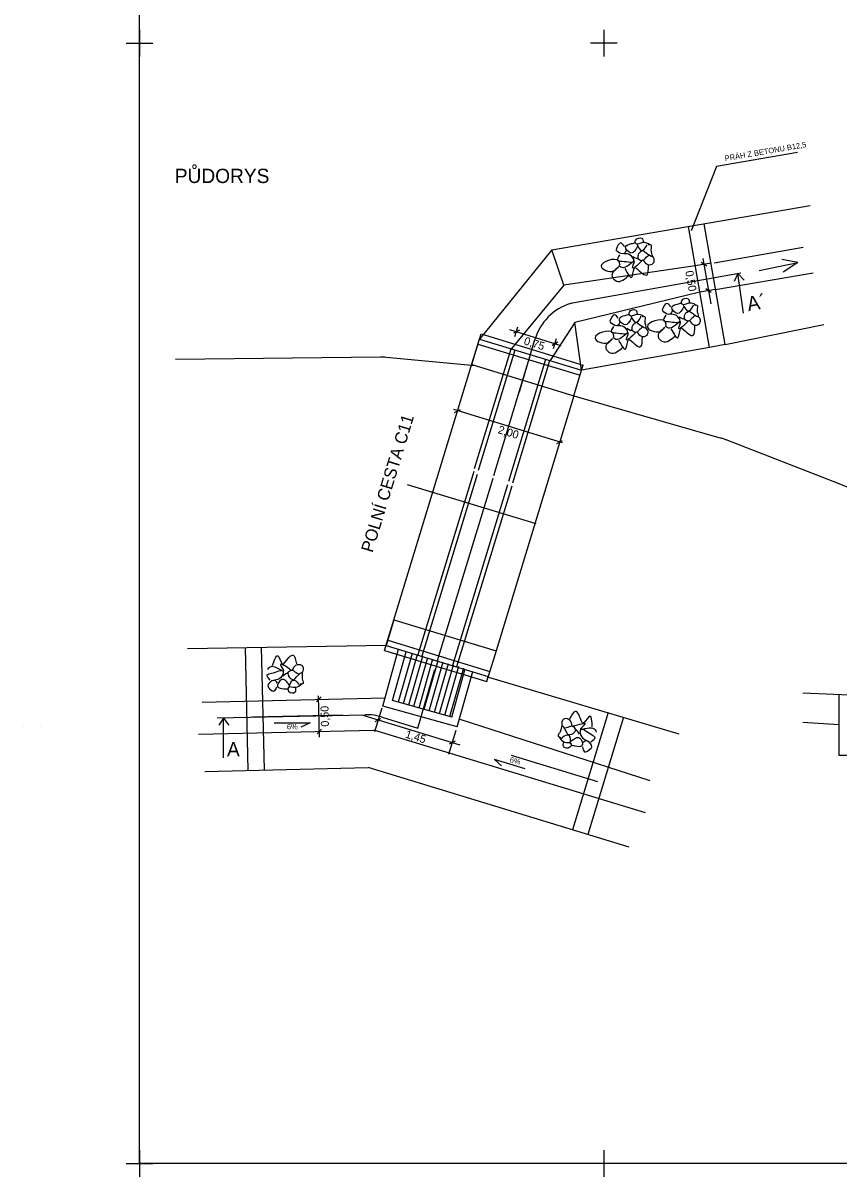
# Model space of a CAD drawing. Extents: x -463095.2 to -463031, y -1105061.3 to -1104976.3.
# Drawn here: x -463095.23 to -463064.66, y -1105061.31 to -1105018.06 of the extents above; entities that cross this region are included whole.
import ezdxf

# ---------------------------------------------------------------- set-up
doc = ezdxf.new("R2010")
doc.units = 0
for name, color, linetype in [('Implicitní', 7, 'Continuous'), ('Vrstva 14', 7, 'Continuous'), ('Vrstva 57', 7, 'Continuous')]:
    doc.layers.add(name, color=color, linetype=linetype)

msp = doc.modelspace()

# ---------------------------------------------------------------- linework, layer by layer
at = {"layer": 'Implicitní'}
for p, q in [((-463073.467, -1105018.311), (-463073.467, -1105019.311)), ((-463073.467, -1105018.311), (-463073.467, -1105019.311)), ((-463072.967, -1105018.811), (-463073.967, -1105018.811)), ((-463072.967, -1105018.811), (-463073.967, -1105018.811)), ((-463073.467, -1105060.311), (-463073.467, -1105061.311)), ((-463073.467, -1105060.311), (-463073.467, -1105061.311)), ((-463072.967, -1105060.811), (-463073.967, -1105060.811)), ((-463072.967, -1105060.811), (-463073.967, -1105060.811))]:
    msp.add_line(p, q, dxfattribs=at)
at = {"layer": 'Vrstva 14'}
for p, q in [((-463090.867, -1105018.311), (-463090.867, -1105019.311)), ((-463090.867, -1105018.312), (-463090.867, -1105019.312)), ((-463091.367, -1105018.811), (-463090.367, -1105018.811)), ((-463091.367, -1105018.812), (-463090.367, -1105018.812)), ((-463066.211, -1105022.907), (-463069.25, -1105023.431)), ((-463069.25, -1105023.431), (-463070.194, -1105025.844)), ((-463075.423, -1105026.566), (-463065.746, -1105024.899)), ((-463068.926, -1105030.115), (-463069.707, -1105025.581)), ((-463069.518, -1105030.217), (-463070.299, -1105025.683)), ((-463075.423, -1105026.566), (-463078.12, -1105029.897)), ((-463074.972, -1105027.879), (-463075.423, -1105026.566)), ((-463069.757, -1105026.885), (-463069.465, -1105028.58)), ((-463069.339, -1105027.046), (-463066.006, -1105026.464)), ((-463070.044, -1105027.162), (-463074.972, -1105027.879)), ((-463069.453, -1105027.06), (-463070.044, -1105027.162)), ((-463069.617, -1105027.179), (-463069.818, -1105027.035)), ((-463067.649, -1105027.337), (-463066.197, -1105027.037)), ((-463066.197, -1105027.037), (-463066.796, -1105026.917)), ((-463066.197, -1105027.037), (-463066.748, -1105027.399)), ((-463069.283, -1105028.045), (-463065.622, -1105027.418)), ((-463068.447, -1105027.453), (-463068.213, -1105027.694)), ((-463074.972, -1105027.879), (-463076.968, -1105030.304)), ((-463069.874, -1105028.147), (-463074.557, -1105029.284)), ((-463069.283, -1105028.045), (-463069.874, -1105028.147)), ((-463069.445, -1105028.162), (-463069.647, -1105028.019)), ((-463076.812, -1105029.811), (-463076.698, -1105029.441)), ((-463074.557, -1105029.284), (-463075.477, -1105030.708)), ((-463074.304, -1105031.072), (-463074.557, -1105029.284)), ((-463068.926, -1105030.115), (-463065.225, -1105029.359)), ((-463081.685, -1105041.577), (-463078.127, -1105029.896)), ((-463078.422, -1105030.863), (-463078.13, -1105029.906)), ((-463078.13, -1105029.906), (-463078.072, -1105029.715)), ((-463078.13, -1105029.906), (-463074.304, -1105031.072)), ((-463078.072, -1105029.715), (-463074.246, -1105030.88)), ((-463077.006, -1105029.551), (-463075.078, -1105030.146)), ((-463076.636, -1105029.566), (-463076.856, -1105029.681)), ((-463075.36, -1105030.26), (-463075.245, -1105029.889)), ((-463078.312, -1105034.758), (-463076.944, -1105030.267)), ((-463078.189, -1105030.097), (-463074.362, -1105031.263)), ((-463078.162, -1105034.814), (-463076.791, -1105030.314)), ((-463076.627, -1105031.88), (-463076.051, -1105029.92)), ((-463075.192, -1105030.027), (-463075.411, -1105030.141)), ((-463069.518, -1105030.217), (-463074.304, -1105031.072)), ((-463068.926, -1105030.115), (-463069.518, -1105030.217)), ((-463081.839, -1105030.583), (-463089.516, -1105030.668)), ((-463078.298, -1105030.911), (-463081.626, -1105030.592)), ((-463077.598, -1105035.023), (-463076.217, -1105030.489)), ((-463077.035, -1105035.234), (-463075.643, -1105030.664)), ((-463076.885, -1105035.291), (-463075.49, -1105030.71)), ((-463078.422, -1105030.863), (-463074.595, -1105032.028)), ((-463074.595, -1105032.028), (-463074.304, -1105031.072)), ((-463074.304, -1105031.072), (-463074.246, -1105030.88)), ((-463073.597, -1105030.945), (-463074.304, -1105031.072)), ((-463074.595, -1105032.028), (-463077.509, -1105041.594)), ((-463074.595, -1105032.028), (-463069.073, -1105033.619)), ((-463075.024, -1105033.79), (-463079.094, -1105032.551)), ((-463079.062, -1105032.663), (-463078.843, -1105032.548)), ((-463075.238, -1105033.822), (-463075.019, -1105033.707)), ((-463068.902, -1105033.676), (-463064.894, -1105035.235)), ((-463078.347, -1105034.873), (-463080.44, -1105041.747)), ((-463078.214, -1105034.986), (-463080.287, -1105041.793)), ((-463080.835, -1105035.355), (-463076.016, -1105036.822)), ((-463077.63, -1105035.128), (-463079.713, -1105041.968)), ((-463077.077, -1105035.37), (-463079.139, -1105042.143)), ((-463076.924, -1105035.417), (-463078.986, -1105042.19)), ((-463064.894, -1105035.235), (-463063.002, -1105035.971)), ((-463081.335, -1105040.429), (-463081.627, -1105041.386)), ((-463081.335, -1105040.429), (-463077.509, -1105041.594)), ((-463081.629, -1105041.39), (-463089.074, -1105041.516)), ((-463086.913, -1105041.472), (-463086.806, -1105046.071)), ((-463086.311, -1105041.458), (-463086.204, -1105046.057)), ((-463081.756, -1105043.668), (-463081.162, -1105041.535)), ((-463081.685, -1105041.577), (-463081.627, -1105041.386)), ((-463081.685, -1105041.577), (-463077.858, -1105042.742)), ((-463081.627, -1105041.386), (-463077.8, -1105042.551)), ((-463081.568, -1105041.194), (-463077.742, -1105042.36)), ((-463077.509, -1105041.594), (-463077.8, -1105042.551)), ((-463081.386, -1105043.459), (-463080.875, -1105041.624)), ((-463080.654, -1105041.688), (-463081.177, -1105043.519)), ((-463080.461, -1105041.743), (-463080.985, -1105043.574)), ((-463080.269, -1105041.798), (-463080.793, -1105043.629)), ((-463080.077, -1105041.853), (-463080.6, -1105043.684)), ((-463079.885, -1105041.908), (-463080.408, -1105043.739)), ((-463079.692, -1105041.963), (-463080.216, -1105043.794)), ((-463079.5, -1105042.018), (-463080.023, -1105043.849)), ((-463079.308, -1105042.073), (-463079.831, -1105043.904)), ((-463079.115, -1105042.128), (-463079.639, -1105043.959)), ((-463078.923, -1105042.183), (-463079.446, -1105044.014)), ((-463078.731, -1105042.238), (-463079.254, -1105044.069)), ((-463079.171, -1105044.076), (-463078.676, -1105042.3)), ((-463078.962, -1105044.446), (-463078.382, -1105042.361)), ((-463077.858, -1105042.742), (-463077.8, -1105042.551)), ((-463077.796, -1105042.573), (-463070.66, -1105044.699)), ((-463084.069, -1105043.319), (-463084.239, -1105043.499)), ((-463084.13, -1105044.827), (-463084.166, -1105043.275)), ((-463066.009, -1105043.16), (-463055.449, -1105043.615)), ((-463064.664, -1105043.218), (-463064.664, -1105044.28)), ((-463088.516, -1105043.51), (-463081.667, -1105043.351)), ((-463081.792, -1105043.737), (-463082.065, -1105044.632)), ((-463078.962, -1105044.446), (-463081.756, -1105043.668)), ((-463079.171, -1105044.076), (-463081.386, -1105043.459)), ((-463087.956, -1105044.105), (-463082.415, -1105043.986)), ((-463087.718, -1105044.109), (-463087.521, -1105044.382)), ((-463086.639, -1105044.067), (-463083.254, -1105043.988)), ((-463078.849, -1105045.124), (-463082.492, -1105044.015)), ((-463082.04, -1105044.24), (-463081.821, -1105044.125)), ((-463071.734, -1105046.469), (-463078.86, -1105044.171)), ((-463073.306, -1105043.899), (-463074.646, -1105048.3)), ((-463072.73, -1105044.075), (-463074.07, -1105048.475)), ((-463064.664, -1105043.946), (-463064.664, -1105044.368)), ((-463095.232, -1105044.423), (-463095.232, -1105044.423)), ((-463094.581, -1105044.423), (-463094.581, -1105044.423)), ((-463088.664, -1105044.714), (-463082.085, -1105044.561)), ((-463084.048, -1105044.528), (-463084.217, -1105044.708)), ((-463071.915, -1105047.668), (-463082.085, -1105044.561)), ((-463079.018, -1105044.581), (-463079.291, -1105045.477)), ((-463064.664, -1105044.368), (-463066.014, -1105044.28)), ((-463064.664, -1105044.28), (-463064.664, -1105045.502)), ((-463079.251, -1105045.077), (-463079.032, -1105044.962)), ((-463073.692, -1105046.499), (-463076.931, -1105045.513)), ((-463064.664, -1105045.502), (-463064.062, -1105045.502)), ((-463088.426, -1105046.109), (-463082.306, -1105045.967)), ((-463072.52, -1105048.947), (-463082.306, -1105045.967)), ((-463090.867, -1105060.311), (-463090.867, -1105061.311)), ((-463091.367, -1105060.811), (-463090.367, -1105060.811))]:
    msp.add_line(p, q, dxfattribs=at)
msp.add_lwpolyline([(-463090.867, -1105060.811), (-463090.867, -1104976.812), (-463031.467, -1104976.812), (-463031.467, -1105060.811)], close=True, dxfattribs=at)
for points in [[(-463074.715, -1105028.571), (-463074.644, -1105028.55), (-463068.343, -1105027.42)], [(-463068.233, -1105028.932), (-463068.447, -1105027.453), (-463068.588, -1105027.748)], [(-463081.773, -1105044.077), (-463080.439, -1105044.496), (-463079.808, -1105042.289)], [(-463087.718, -1105045.603), (-463087.718, -1105044.109), (-463087.9, -1105044.382)], [(-463085.829, -1105044.285), (-463084.48, -1105044.285), (-463084.824, -1105044.449)], [(-463076.425, -1105046.02), (-463077.565, -1105045.669), (-463077.304, -1105045.9)]]:
    msp.add_lwpolyline(points, dxfattribs=at)
for centre, start, end in [((-463074.132, -1105030.484), 106.9595, 163.6136), ((-463081.817, -1105032.583), 84.5379, 90.6298), ((-463069.627, -1105035.541), 68.7557, 73.9322), ((-463082.372, -1105045.985), 72.5665, 91.2363)]:
    msp.add_arc(centre, 2, start, end, dxfattribs=at)
for points in [[(-463072.698, -1105026.434), (-463072.84, -1105026.302), (-463073.013, -1105026.547)], [(-463072.209, -1105026.42), (-463072.453, -1105026.68), (-463072.658, -1105026.451), (-463072.44, -1105026.328), (-463072.29, -1105026.29)], [(-463071.738, -1105026.376), (-463072.016, -1105026.292), (-463072.272, -1105026.336), (-463072.283, -1105026.206), (-463072.044, -1105026.128), (-463071.995, -1105026.276)], [(-463072.237, -1105026.33), (-463072.037, -1105026.584), (-463071.874, -1105026.424), (-463071.848, -1105026.358)], [(-463072.013, -1105026.579), (-463071.656, -1105026.782), (-463071.694, -1105026.561), (-463071.7, -1105026.381), (-463071.809, -1105026.376)], [(-463072.864, -1105027.134), (-463072.91, -1105026.984), (-463073.569, -1105027.176), (-463073.104, -1105027.354), (-463072.947, -1105027.227)], [(-463072.636, -1105026.579), (-463072.711, -1105026.7), (-463072.95, -1105026.633), (-463073.011, -1105026.559)], [(-463072.884, -1105026.742), (-463072.955, -1105026.959), (-463072.781, -1105026.988), (-463072.341, -1105026.973), (-463072.486, -1105026.756), (-463072.721, -1105026.714)], [(-463072.381, -1105026.811), (-463072.19, -1105026.874), (-463072.176, -1105026.752), (-463072.035, -1105026.595)], [(-463072.224, -1105026.863), (-463071.986, -1105026.948), (-463071.916, -1105026.875), (-463071.758, -1105026.74)], [(-463071.997, -1105026.944), (-463071.826, -1105027.111), (-463071.619, -1105027.064), (-463071.58, -1105026.937), (-463071.666, -1105026.779)], [(-463072.913, -1105027.201), (-463073.165, -1105027.563), (-463072.998, -1105027.731), (-463072.522, -1105027.511)], [(-463072.012, -1105026.94), (-463072.394, -1105027.221), (-463072.325, -1105026.994), (-463072.739, -1105027.232), (-463072.909, -1105027.154)], [(-463072.688, -1105027.26), (-463072.426, -1105027.588), (-463072.329, -1105027.259), (-463072.291, -1105027.192)], [(-463072.274, -1105027.231), (-463071.853, -1105027.496), (-463071.795, -1105027.149)], [(-463070.966, -1105028.698), (-463071.109, -1105028.567), (-463071.282, -1105028.812)], [(-463070.477, -1105028.685), (-463070.721, -1105028.944), (-463070.927, -1105028.716), (-463070.708, -1105028.593), (-463070.559, -1105028.555)], [(-463070.006, -1105028.641), (-463070.285, -1105028.557), (-463070.541, -1105028.601), (-463070.551, -1105028.471), (-463070.313, -1105028.393), (-463070.263, -1105028.541)], [(-463070.505, -1105028.595), (-463070.305, -1105028.848), (-463070.142, -1105028.688), (-463070.117, -1105028.623)], [(-463072.929, -1105029.124), (-463073.071, -1105028.992), (-463073.244, -1105029.237)], [(-463072.44, -1105029.111), (-463072.683, -1105029.37), (-463072.889, -1105029.141), (-463072.671, -1105029.018), (-463072.521, -1105028.981)], [(-463071.968, -1105029.066), (-463072.247, -1105028.982), (-463072.503, -1105029.026), (-463072.513, -1105028.896), (-463072.275, -1105028.818), (-463072.225, -1105028.966)], [(-463072.468, -1105029.02), (-463072.268, -1105029.274), (-463072.104, -1105029.114), (-463072.079, -1105029.048)], [(-463070.905, -1105028.844), (-463070.979, -1105028.965), (-463071.218, -1105028.898), (-463071.28, -1105028.823)], [(-463071.153, -1105029.007), (-463071.223, -1105029.224), (-463071.049, -1105029.253), (-463070.61, -1105029.238), (-463070.754, -1105029.021), (-463070.989, -1105028.978)], [(-463070.65, -1105029.076), (-463070.458, -1105029.139), (-463070.445, -1105029.017), (-463070.303, -1105028.86)], [(-463070.492, -1105029.128), (-463070.255, -1105029.213), (-463070.184, -1105029.14), (-463070.027, -1105029.005)], [(-463070.282, -1105028.844), (-463069.924, -1105029.047), (-463069.962, -1105028.826), (-463069.969, -1105028.646), (-463070.077, -1105028.641)], [(-463070.265, -1105029.209), (-463070.095, -1105029.376), (-463069.888, -1105029.328), (-463069.849, -1105029.202), (-463069.935, -1105029.044)], [(-463072.867, -1105029.269), (-463072.942, -1105029.39), (-463073.18, -1105029.323), (-463073.242, -1105029.249)], [(-463073.115, -1105029.432), (-463073.185, -1105029.649), (-463073.012, -1105029.678), (-463072.572, -1105029.663), (-463072.717, -1105029.447), (-463072.951, -1105029.404)], [(-463072.612, -1105029.502), (-463072.42, -1105029.564), (-463072.407, -1105029.442), (-463072.266, -1105029.286)], [(-463072.455, -1105029.554), (-463072.217, -1105029.638), (-463072.146, -1105029.565), (-463071.989, -1105029.431)], [(-463072.244, -1105029.27), (-463071.886, -1105029.472), (-463071.924, -1105029.251), (-463071.931, -1105029.072), (-463072.04, -1105029.066)], [(-463072.228, -1105029.634), (-463072.057, -1105029.802), (-463071.85, -1105029.754), (-463071.811, -1105029.627), (-463071.897, -1105029.47)], [(-463071.132, -1105029.399), (-463071.178, -1105029.248), (-463071.837, -1105029.441), (-463071.372, -1105029.619), (-463071.215, -1105029.492)], [(-463071.181, -1105029.466), (-463071.433, -1105029.828), (-463071.266, -1105029.996), (-463070.791, -1105029.776)], [(-463070.28, -1105029.205), (-463070.662, -1105029.486), (-463070.594, -1105029.259), (-463071.007, -1105029.497), (-463071.177, -1105029.419)], [(-463070.956, -1105029.525), (-463070.694, -1105029.853), (-463070.597, -1105029.524), (-463070.56, -1105029.456)], [(-463070.543, -1105029.496), (-463070.122, -1105029.76), (-463070.064, -1105029.414)], [(-463073.094, -1105029.824), (-463073.14, -1105029.674), (-463073.799, -1105029.866), (-463073.334, -1105030.044), (-463073.177, -1105029.918)], [(-463073.143, -1105029.891), (-463073.396, -1105030.253), (-463073.229, -1105030.422), (-463072.753, -1105030.202)], [(-463072.243, -1105029.631), (-463072.624, -1105029.912), (-463072.556, -1105029.685), (-463072.97, -1105029.922), (-463073.139, -1105029.844)], [(-463072.918, -1105029.95), (-463072.657, -1105030.278), (-463072.559, -1105029.949), (-463072.522, -1105029.882)], [(-463072.505, -1105029.921), (-463072.084, -1105030.186), (-463072.026, -1105029.839)], [(-463085.157, -1105042.33), (-463085.585, -1105042.128), (-463085.474, -1105042.337), (-463085.926, -1105042.184), (-463086.078, -1105042.293)], [(-463085.881, -1105042.147), (-463085.688, -1105041.774), (-463085.528, -1105042.078), (-463085.479, -1105042.137)], [(-463085.47, -1105042.095), (-463085.108, -1105041.754), (-463084.984, -1105042.084)], [(-463085.974, -1105042.693), (-463086.085, -1105042.493), (-463085.92, -1105042.432), (-463085.486, -1105042.361), (-463085.586, -1105042.602), (-463085.808, -1105042.689)], [(-463085.494, -1105042.528), (-463085.318, -1105042.43), (-463085.282, -1105042.547), (-463085.113, -1105042.673)], [(-463085.35, -1105042.446), (-463085.133, -1105042.317), (-463085.049, -1105042.375), (-463084.869, -1105042.477)], [(-463085.143, -1105042.323), (-463085.007, -1105042.126), (-463084.795, -1105042.133), (-463084.732, -1105042.25), (-463084.786, -1105042.421)], [(-463085.088, -1105042.684), (-463084.776, -1105042.417), (-463084.771, -1105042.641), (-463084.743, -1105042.818), (-463084.849, -1105042.845)], [(-463085.7, -1105042.804), (-463085.796, -1105042.701), (-463086.018, -1105042.812), (-463086.064, -1105042.897)], [(-463085.25, -1105042.878), (-463085.539, -1105042.671), (-463085.697, -1105042.934), (-463085.459, -1105043.013), (-463085.305, -1105043.021)], [(-463084.779, -1105042.831), (-463085.036, -1105042.967), (-463085.296, -1105042.973), (-463085.281, -1105043.103), (-463085.032, -1105043.133), (-463085.011, -1105042.979)], [(-463085.26, -1105042.972), (-463085.112, -1105042.685), (-463084.921, -1105042.81), (-463084.884, -1105042.87)], [(-463085.732, -1105042.959), (-463085.847, -1105043.116), (-463086.063, -1105042.909)], [(-463074.664, -1105044.418), (-463074.741, -1105044.192), (-463074.947, -1105044.141), (-463075.039, -1105044.237), (-463075.033, -1105044.416)], [(-463074.287, -1105044.286), (-463074.544, -1105043.861), (-463074.752, -1105044.144)], [(-463073.905, -1105044.446), (-463073.991, -1105044.035), (-463074.226, -1105044.286), (-463074.289, -1105044.329)], [(-463074.813, -1105044.751), (-463075.042, -1105044.409), (-463075.107, -1105044.624), (-463075.182, -1105044.787), (-463075.087, -1105044.841)], [(-463074.497, -1105044.592), (-463074.671, -1105044.409), (-463074.767, -1105044.443), (-463074.968, -1105044.492)], [(-463074.38, -1105044.709), (-463074.523, -1105044.567), (-463074.59, -1105044.67), (-463074.787, -1105044.746)], [(-463074.652, -1105044.428), (-463074.185, -1105044.349), (-463074.348, -1105044.52), (-463073.871, -1105044.494), (-463073.755, -1105044.64)], [(-463073.962, -1105044.998), (-463073.802, -1105044.835), (-463073.944, -1105044.731), (-463074.343, -1105044.547), (-463074.311, -1105044.805), (-463074.121, -1105044.949)], [(-463075.151, -1105044.809), (-463074.94, -1105045.009), (-463074.691, -1105045.085), (-463074.74, -1105045.206), (-463074.988, -1105045.168), (-463074.966, -1105045.014)], [(-463074.726, -1105045.074), (-463074.79, -1105044.758), (-463075.008, -1105044.827), (-463075.06, -1105044.874)], [(-463074.71, -1105044.981), (-463074.376, -1105044.859), (-463074.294, -1105045.156), (-463074.545, -1105045.167), (-463074.696, -1105045.134)], [(-463074.257, -1105045.031), (-463074.136, -1105044.957), (-463073.952, -1105045.124), (-463073.931, -1105045.218)], [(-463074.267, -1105045.189), (-463074.199, -1105045.371), (-463073.934, -1105045.23)]]:
    msp.add_spline(points, degree=3, dxfattribs=at)

# ---------------------------------------------------------------- texts
for s, p in [('PŮDORYS', (-463089.547, -1105024.057)), ('A', (-463087.592, -1105045.55))]:
    msp.add_text(s, height=0.536, dxfattribs=at).set_placement(p)
for s, height, rotation, p in [('0,50', 0.3, 279.7756, (-463070.42, -1105027.368)), ('A´', 0.536, 10.3108, (-463068.054, -1105028.863)), ('0,75', 0.3, 342.8458, (-463076.491, -1105030.101)), ('2,00', 0.3, 343.0608, (-463077.461, -1105033.426)), ('0,50', 0.3, 91.3295, (-463083.771, -1105044.43)), ('1,45', 0.3, 343.0608, (-463080.936, -1105044.839))]:
    msp.add_text(s, height=height, rotation=rotation, dxfattribs=at).set_placement(p)
at = {"layer": 'Vrstva 57'}
for s, height, rotation, p in [('PRÁH Z BETONU B12,5', 0.204, 9.7756, (-463068.923, -1105023.236)), ('POLNÍ CESTA C11', 0.459, 73.0608, (-463082.139, -1105037.935)), ('6%', 0.204, 345.9558, (-463077.014, -1105045.764))]:
    msp.add_text(s, height=height, rotation=rotation, dxfattribs=at).set_placement(p)
msp.add_text('6%', height=0.204, dxfattribs=at).set_placement((-463085.347, -1105044.535))

doc.saveas('drawing.dxf')
